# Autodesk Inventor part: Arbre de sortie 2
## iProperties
Shininess: 64.0
Length Units: 11269
Angle Units: 11279
Time Units: 11290
Mass Units: 11283
Length Display Precision: 3
Angle Display Precision: 2
Compacted: True
Part Number: Arbre de sortie 2
Document SubType Name: Modeling
Created: 2004-09
Material: Par défaut
Designer: Laurent
Density: 1 g/cm^3
Density: 0.0
Volumn: 0.0
Area: 0.0
PropertySet Name: Model Information
Control State: 0
Master: False
Checked Out: False
Author: Laurent
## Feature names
1. Extrusion1
2. Extrusion2
3. Extrusion3
4. Extrusion4
5. Extrusion5
6. Extrusion6
7. Extrusion7
8. Extrusion8
9. Congé1 [Fillet]
10. Chanfrein1 [Chamfer]
11. Chanfrein2 [Chamfer]
12. Chanfrein3 [Chamfer]
13. Extrusion9
14. Perçage1 [Hole]
15. Chanfrein4 [Chamfer]
16. Perçage2 [Hole]
17. Réseau circulaire1 [Circular Pattern]
18. Chanfrein5 [Chamfer]
19. Révolution1 [Revolution]
20. Extrusion10
21. Révolution2 [Revolution]
